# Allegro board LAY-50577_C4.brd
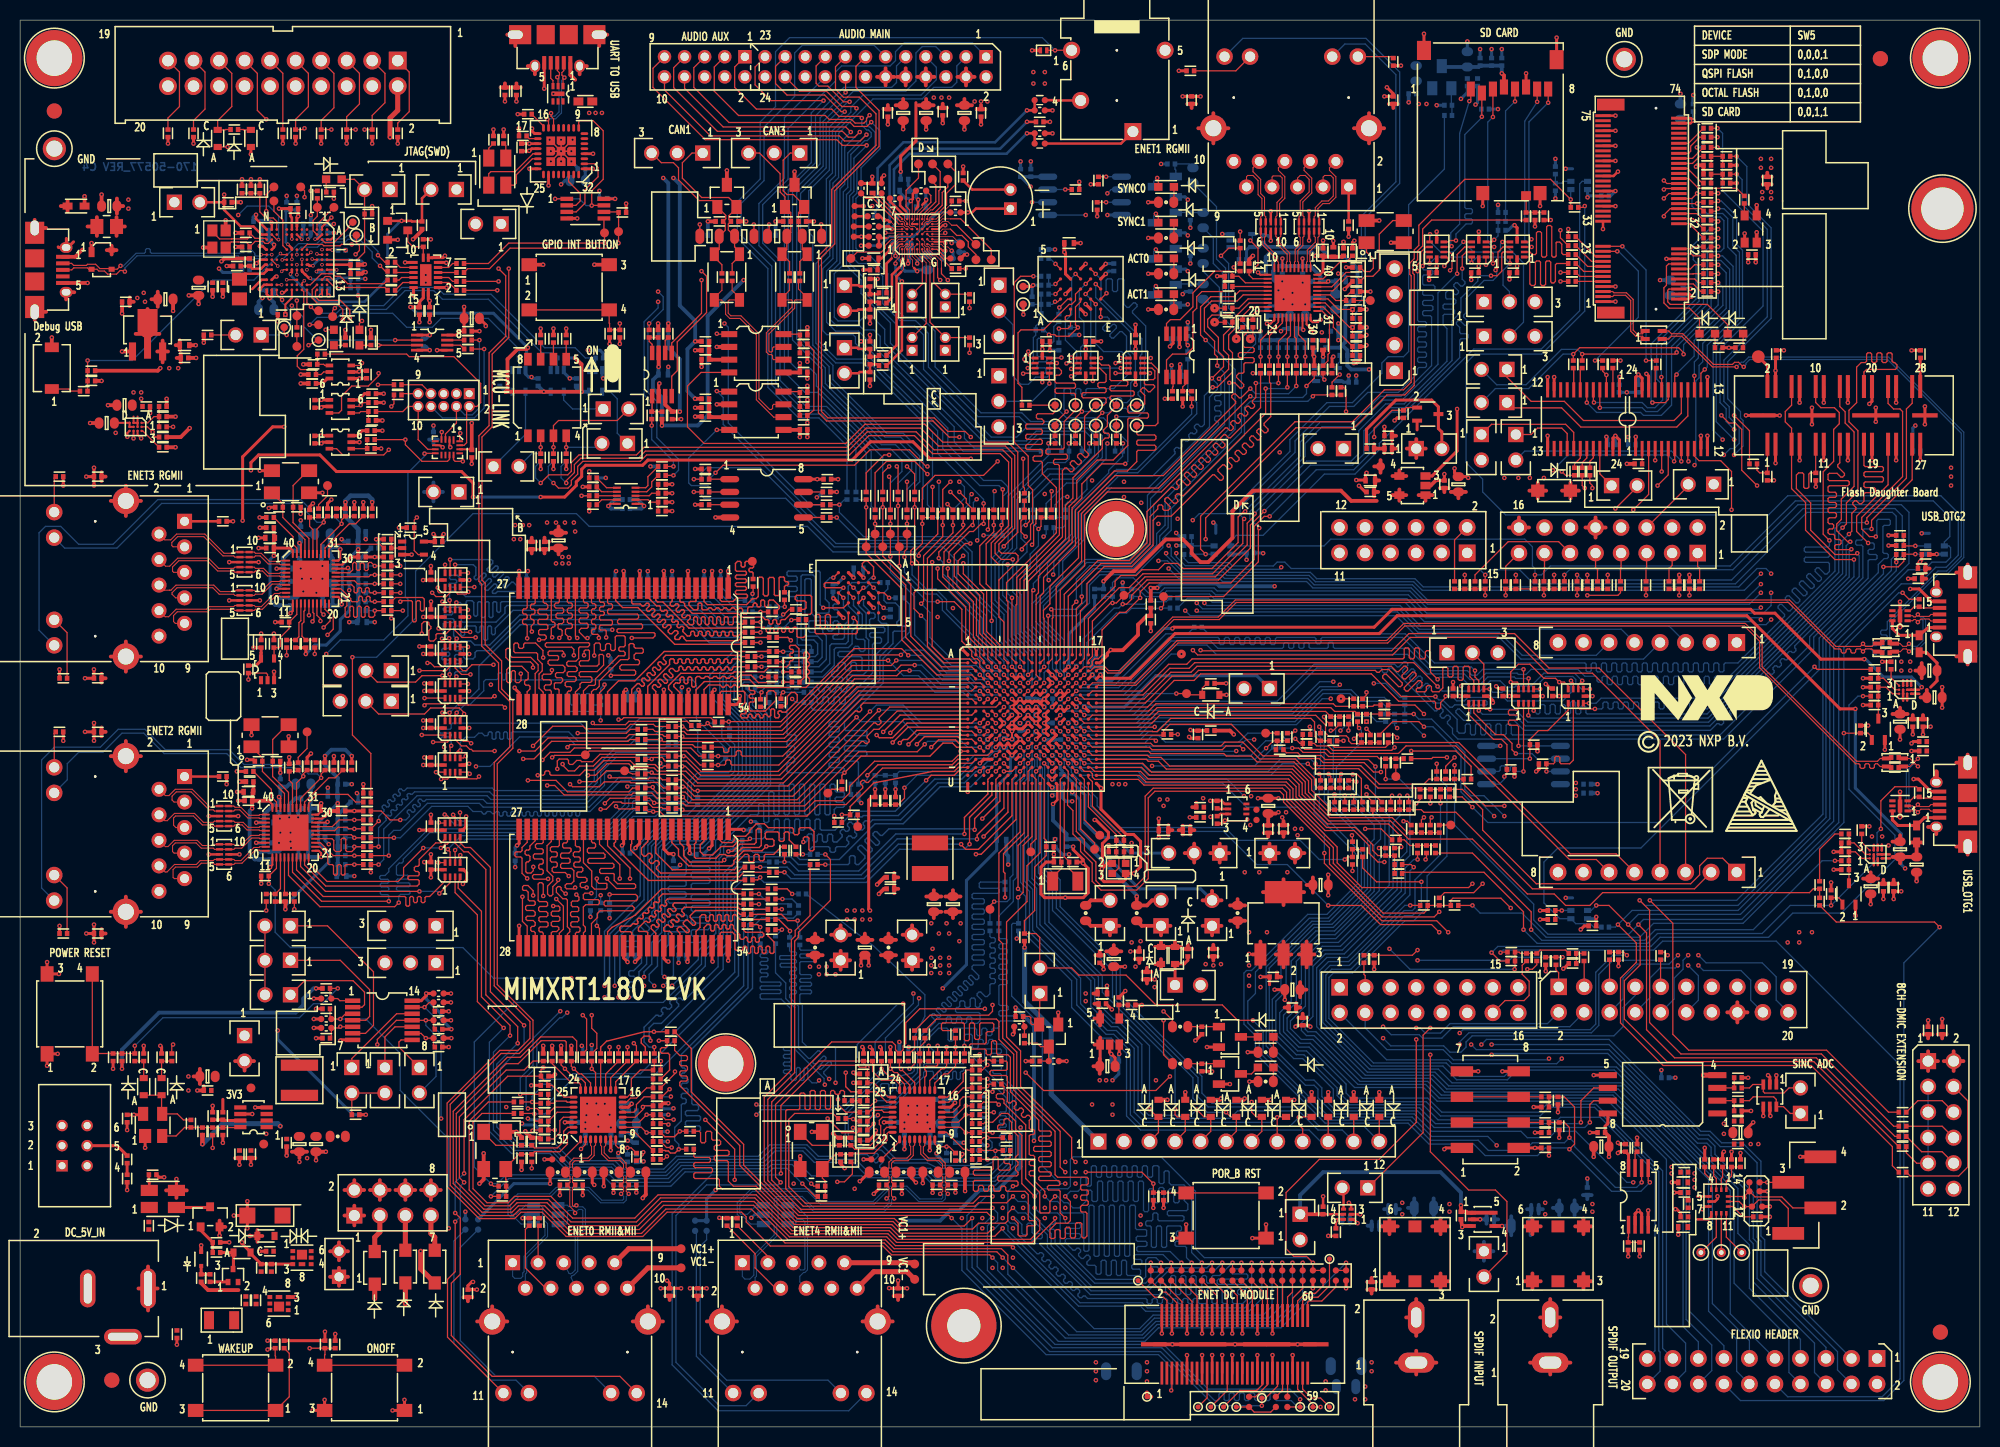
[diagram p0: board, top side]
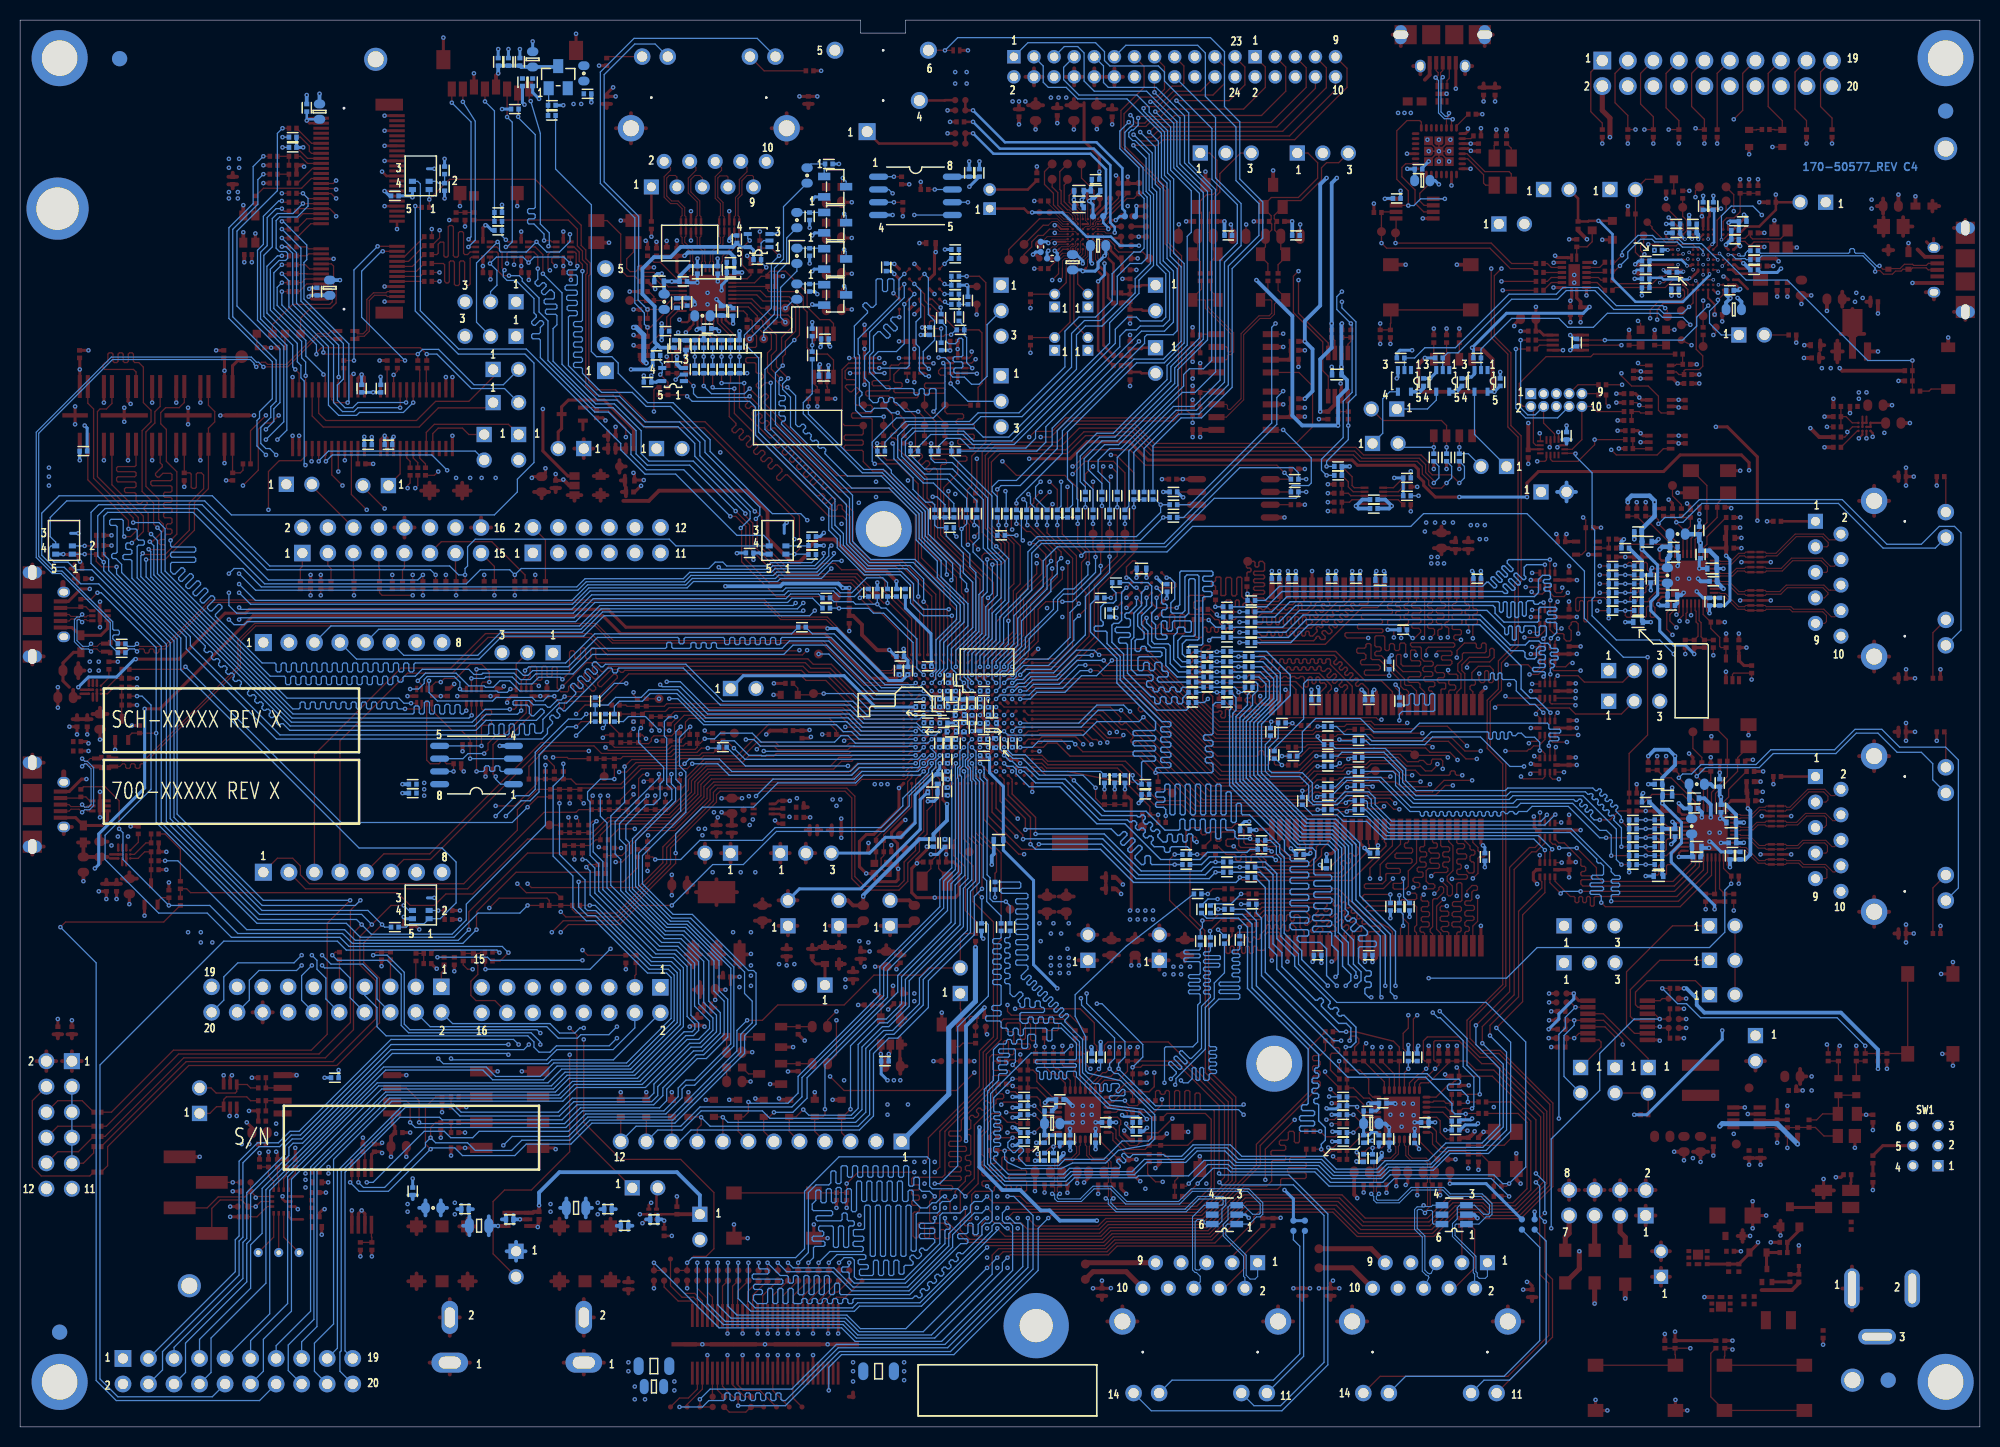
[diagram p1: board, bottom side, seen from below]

Outline 195 x 140 mm; copper layers: TOP, L2_GND_1, L3_INT_1, L4_PWR_1, L5_GND_2, BOTTOM. Coordinates in mm from the lower left corner of the outline.
Outline path: 0,140 106.88,140 106.88,138.71 111.37,138.71 111.37,140 195,140 195,0 0,0 0,140

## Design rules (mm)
constraint set DEFAULT: min track width 0.127
net group CAN1: nets N103603009 N103603017
net group CAN2: nets N100797464 N100797616
net group DBUG_USB_D: nets DBUG_USB_DM DBUG_USB_DP
net group DP1-USB: nets N101733827 N101733829
net group DP_N99833038: nets N99833038 N99833048
net group DP_N100169943: nets N100169943 N100169951
net group DP_OTG1: nets OTG1_DN OTG1_DP
net group DP_OTG2: nets OTG2_DN OTG2_DP
net group ECAT0_RX_DV: nets ECAT0_RX_DV PHY0_RXDV
net group ECAT0_RXCLK: nets ECAT0_RXCLK PHY0_RXC
net group ECAT0_RXD2: nets ECAT0_RXD2 PHY0_RXD2_INTB
net group ECAT0_RXD3: nets ECAT0_RXD3 PHY0_RXD3
net group ENET1_RGMII_RX_EN: nets ENET1_RGMII_RX_EN RXCTL_PHYAD2_1
net group ENET1_RGMII_RXC: nets ENET1_RGMII_RXC RXC_PHYAD1_1
net group ENET1_RGMII_RXD0: nets ENET1_RGMII_RXD0 RXD0_RXDLY_1
net group ENET1_RGMII_RXD1: nets ENET1_RGMII_RXD1 RXD1_TXDLY_1
net group ENET1_RGMII_RXD2: nets ENET1_RGMII_RXD2 RXD2_PLLOFF_1
net group ENET1_RGMII_RXD3: nets ENET1_RGMII_RXD3 RXD3_PHYAD0_1
net group ETH1_TRX0: nets PHY1_TRX0_N PHY1_TRX0_P
net group ETH1_TRX1: nets PHY1_TRX1_N PHY1_TRX1_P
net group ETH1_TRX2_: nets PHY1_TRX2_N PHY1_TRX2_P
net group ETH1_TRX3_: nets PHY1_TRX3_N PHY1_TRX3_P
net group ETH2_TRX0_: nets PHY2_TRX0_N PHY2_TRX0_P
net group ETH2_TRX1_: nets PHY2_TRX1_N PHY2_TRX1_P
net group ETH2_TRX2_: nets PHY2_TRX2_N PHY2_TRX2_P
net group ETH2_TRX3_: nets PHY2_TRX3_N PHY2_TRX3_P
net group ETH3_TRX0_: nets PHY3_TRX0_N PHY3_TRX0_P
net group ETH3_TRX1_: nets PHY3_TRX1_N PHY3_TRX1_P
net group ETH3_TRX2_: nets PHY3_TRX2_N PHY3_TRX2_P
net group ETH3_TRX3_: nets PHY3_TRX3_N PHY3_TRX3_P
net group FLEXSPI1_A_D4: nets FLEXSPI1_A_D4 GPIO_B2_03
net group FLEXSPI1_A_D5: nets FLEXSPI1_A_D5 GPIO_B2_04
net group FLEXSPI1_A_D6: nets FLEXSPI1_A_D6 GPIO_B2_05
net group FLEXSPI1_A_D7: nets FLEXSPI1_A_D7 GPIO_B2_06
net group FLEXSPI1_A_SS0_8: nets FLEXSPI1_A_SS0_8 N103609361
net group FLEXSPI2_A_SS0: nets FLEXSPI2_A_SS0 GPIO_EMC_B1_39_P
net group GPIO_EMC_B2_02: nets GPIO_EMC_B2_02 SEMC_D18
net group N103961253: nets N103961253 N103962432
net group N103961260: nets N103961260 N103962456
net group N105541476: nets N105541476 N105544244
net group PHY0_MDI0: nets PHY0_MDI0+ PHY0_MDI0-
net group PHY0_MDI1: nets PHY0_MDI1+ PHY0_MDI1-
net group PHY0_TXD2: nets ECAT0_TXD2 PHY0_TXD2
net group PHY0_TXD3: nets ECAT0_TXD3 PHY0_TXD3
net group PHY3_RGMII_RX_EN: nets PHY3_RGMII_RX_EN RXCTL_PHYAD2_3
net group PHY3_RGMII_RXC: nets PHY3_RGMII_RXC RXC_PHYAD1_3
net group PHY3_RGMII_RXD0: nets PHY3_RGMII_RXD0 RXD0_RXDLY_3
net group PHY3_RGMII_RXD1: nets PHY3_RGMII_RXD1 RXD1_TXDLY_3
net group PHY3_RGMII_RXD2: nets PHY3_RGMII_RXD2 RXD2_PLLOFF_3
net group PHY3_RGMII_RXD3: nets PHY3_RGMII_RXD3 RXD3_PHYAD0_3
net group PHY4_MDI0: nets PHY4_MDI0+ PHY4_MDI0-
net group PHY4_MDI1: nets PHY4_MDI1+ PHY4_MDI1-
net group SD1_CLK: nets N100768470 SD1_CLK
net group SD_PWREN_B: nets N101370712 SD_PWREN_B
net group SEMC_A5: nets GPIO_EMC_B1_14 SEMC_A5
net group SEMC_A6: nets GPIO_EMC_B1_15 SEMC_A6
net group SEMC_A9: nets GPIO_EMC_B1_18 SEMC_A9
net group SEMC_A11: nets GPIO_EMC_B1_19 SEMC_A11
net group SEMC_CKE: nets GPIO_EMC_B1_27 SEMC_CKE
net group SEMC_CS0: nets GPIO_EMC_B1_29 SEMC_CS0
net group SEMC_D19: nets GPIO_EMC_B2_03 SEMC_D19
net group SEMC_D20: nets GPIO_EMC_B2_04 SEMC_D20
net group SEMC_WE: nets GPIO_EMC_B1_28 SEMC_WE
net group USB-A: nets N101733775 N101733777
net group WIFI_SDIO_CLK: nets N101734331 WIFI_SDIO_CLK
net group WIFI_SDIO_CMD: nets N101734351 WIFI_SDIO_CMD
net group WIFI_SDIO_D0: nets N101734355 WIFI_SDIO_D0
net group WIFI_SDIO_D1: nets N101734367 WIFI_SDIO_D1
net group WIFI_SDIO_D2: nets N101734379 WIFI_SDIO_D2
net group WIFI_SDIO_D3: nets N101734391 WIFI_SDIO_D3
net group 3W: nets AUD_INT DMIC_CLK JTAG_DACK JTAG_NSRST JTAG_RTCK JTAG_TCK SAI1_MCLK SAI1_RX_BCLK SAI1_TX_BCLK
net group CONN_ENET_RD2: nets CONN_ENET_RD2 ECAT0_RXD1 ENET0_RXD1 ENET4_RGMII_RXD2 GPIO_EMC_B2_10 PHY0_RXD1 SEMC_D25
net group CONN_ENET_RD3: nets CONN_ENET_RD3 ECAT0_RXD0 ENET0_RXD0 ENET4_RGMII_RXD3 GPIO_EMC_B2_09 PHY0_RXD0 SEMC_D24
net group CONN_ENET_RXC: nets CONN_ENET_RXC ECAT0_TX_REF_CLK ENET0_TX_REF_CLK ENET4_RGMII_RXC GPIO_EMC_B2_08 PHY0_TXC SEMC_DM2
net group ECAT1-TX(U123): nets ECAT1_TX_REF_CLK ECAT1_TXD0 ECAT1_TXD1 ECAT1_TXEN
net group ECAT1_RX_DV: nets ECAT1_RX_DV FLEXSPI2_B_D1 GPIO_EMC_B1_32_P PHY4_RXDV SEMC_D10
net group ECAT1_RXCLK: nets ECAT1_RXCLK FLEXSPI2_A_D3 GPIO_EMC_B1_38_P PHY4_RXC SEMC_DM1
net group ECAT1_RXD0: nets CONN_ENET_RD0 ECAT1_RXD0 ENET4_RGMII_RXD0 ENET4_RXD0 FLEXSPI2_B_D3 GPIO_EMC_B1_30_P GPIO_EMC_B2_17 PHY4_RXD0 SEMC_D8 SEMC_DM3
net group ECAT1_RXD1: nets CONN_ENET_RD1 ECAT1_RXD1 ENET4_RGMII_RXD1 ENET4_RXD1 FLEXSPI2_B_D2 GPIO_EMC_B1_31_P GPIO_EMC_B2_18 PHY4_RXD1 SEMC_D9
net group ECAT1_RXD2: nets ECAT1_RXD2 FLEXSPI2_B_CLK GPIO_EMC_B1_34_P PHY4_RXD2_INTB SEMC_D12
net group ECAT1_RXD3: nets ECAT1_RXD3 FLEXSPI2_A_D0 GPIO_EMC_B1_35_P PHY4_RXD3 SEMC_D13
net group ECAT1_RXER: nets ECAT1_RXER ENET4_RXER FLEXSPI2_B_D0 GPIO_EMC_B1_33_P GPIO_EMC_B2_20 PHY4_RXER/FXEN SEMC_D11
net group ECAT1_TXD2: nets ECAT1_TXD2 FLEXSPI2_A_D2 GPIO_EMC_B1_37_P PHY4_TXD2 SEMC_D15
net group ECAT1_TXD3: nets ECAT1_TXD3 FLEXSPI2_A_D1 GPIO_EMC_B1_36_P PHY4_TXD3 SEMC_D14
net group ENET2_MII_CRS: nets CONN_ENET_RX_CTL ENET2_MII_CRS ENET4_CRS_DV ENET4_RGMII_RX_EN FLEXSPI2_A_DQS GPIO_EMC_B1_40_P GPIO_EMC_B2_19 PHY4_CRS_DV
net group ENET2_RGMII_TXD2: nets ENET2_RGMII_TXD2 GPIO_EMC_B1_25 SEMC_RAS
net group ENET2_RGMII_TXD3: nets ENET2_RGMII_TXD3 GPIO_EMC_B1_24 SEMC_CAS
net group FLEXSPI1_A-A: nets FLEXSPI1_A_CLK_8 FLEXSPI1_A_D0_8 FLEXSPI1_A_D1_8 FLEXSPI1_A_D2_8 FLEXSPI1_A_D3_8 N103609386
net group FLEXSPI1_A-P: nets FLEXSPI1_A_CLK FLEXSPI1_A_D0 FLEXSPI1_A_D1 FLEXSPI1_A_D2 FLEXSPI1_A_D3 FLEXSPI1_A_DQS FLEXSPI1_A_SS0
net group FLEXSPI1_A-U12: nets FLEXSPI1_A_CLK_4 FLEXSPI1_A_D0_4 FLEXSPI1_A_D1_4 FLEXSPI1_A_D2_4 FLEXSPI1_A_D3_4 FLEXSPI1_A_SS0_4
net group FLEXSPI1_B-P-U6-J71: nets FLEXSPI1_B_D4 FLEXSPI1_B_D5 FLEXSPI1_B_D6 FLEXSPI1_B_D7 FLEXSPI1_B_DQS
net group FLEXSPI1_B-SWITCH-J71: nets FLEXSPI1_B_CLK_8 FLEXSPI1_B_D0_8 FLEXSPI1_B_D1_8 FLEXSPI1_B_D2_8 FLEXSPI1_B_D3_8 FLEXSPI1_B_SS0_8
net group FLEXSPI1_B-SWITHC-U10: nets FLEXSPI1_B_CLK_4 FLEXSPI1_B_D0_4 FLEXSPI1_B_D1_4 FLEXSPI1_B_D2_4 FLEXSPI1_B_D3_4 FLEXSPI1_B_SS0_4
net group FLEXSPI2_A_CLK: nets ENET2_MII_COL FLEXSPI2_A_CLK GPIO_EMC_B1_41_P PHY4_COL
net group FLEXSPI_B-U6-SWITCH: nets FLEXSPI1_B_CLK FLEXSPI1_B_D0 FLEXSPI1_B_D1 FLEXSPI1_B_D2 FLEXSPI1_B_D3 FLEXSPI1_B_SS0
net group GPIO_EMC_B1_00: nets GPIO_EMC_B1_00 GPIO_EMC_B1_00_P SEMC_D0
net group GPIO_EMC_B1_01: nets GPIO_EMC_B1_01 GPIO_EMC_B1_01_P SEMC_D1
net group GPIO_EMC_B1_02: nets GPIO_EMC_B1_02 GPIO_EMC_B1_02_P SEMC_D2
net group GPIO_EMC_B1_03: nets GPIO_EMC_B1_03 GPIO_EMC_B1_03_P SEMC_D3
net group GPIO_EMC_B1_04: nets GPIO_EMC_B1_04 GPIO_EMC_B1_04_P SEMC_D4
net group GPIO_EMC_B1_05: nets GPIO_EMC_B1_05 GPIO_EMC_B1_05_P SEMC_D5
net group GPIO_EMC_B1_06: nets GPIO_EMC_B1_06 GPIO_EMC_B1_06_P SEMC_D6
net group GPIO_EMC_B1_07: nets GPIO_EMC_B1_07 GPIO_EMC_B1_07_P SEMC_D7
net group GPIO_EMC_B1_08: nets GPIO_EMC_B1_08 GPIO_EMC_B1_08_P SEMC_DM0
net group PHY0_TXD0: nets ECAT0_TXD0 ENET0_TXD0 GPIO_EMC_B2_05 PHY0_TXD0 SEMC_D21
net group PHY0_TXD1: nets ECAT0_TXD1 ENET0_TXD1 GPIO_EMC_B2_06 PHY0_TXD1 SEMC_D22
net group PHY0_TXEN: nets ECAT0_TXEN ENET0_TXEN GPIO_EMC_B2_07 PHY0_TXEN SEMC_D23
net group PHY2-RGMII_TX(U29): nets PHY2_RGMII_TX_EN PHY2_RGMII_TXC PHY2_RGMII_TXD0 PHY2_RGMII_TXD1
net group PHY3-RGMII-TX(U34): nets PHY3_RGMII_TX_EN PHY3_RGMII_TXC PHY3_RGMII_TXD0 PHY3_RGMII_TXD1 PHY3_RGMII_TXD2 PHY3_RGMII_TXD3
net group PHY4_TXD0: nets CONN_ENET_TD0 ENET4_RGMII_TXD0 ENET4_TXD0 GPIO_EMC_B2_13 PHY4_TXD0 SEMC_D28
net group PHY4_TXD1: nets CONN_ENET_TD1 ENET4_RGMII_TXD1 ENET4_TXD1 GPIO_EMC_B2_14 PHY4_TXD1 SEMC_D29
net group PHY4_TXEN: nets CONN_ENET_TX_CTL ENET4_RGMII_TX_EN ENET4_TXEN GPIO_EMC_B2_15 PHY4_TXEN SEMC_D30
net group POWER: nets DCDC_1V8_OUT FDC_ECC GND_RJ45_SHELL0 GND_RJ45_SHELL1 GND_RJ45_SHELL2 GND_RJ45_SHELL3 GND_RJ45_SHELL4 N99833017 N100054135 N100054253 N100054255 N100054568 N100169932 N100310756 N100526140 N100538772 N101241745 N102544921 PHY1_AVDD10 PHY1_AVDD33 PHY1_DVDD10 PHY2_AVDD10 PHY2_AVDD33 PHY2_DVDD10 PHY2_DVDDRG PHY3_AVDD10 PHY3_AVDD33 PHY3_DVDD10 PHY3_DVDD33 PHY3_DVDDRG PHY4_3V3 SPDIF_VCC VDD_AON_ANA VDD_AON_DIG VDD_BBSM_ANA VDD_BBSM_IN VDD_COIN_3V VDD_USB_1P8 VDD_USB_3P3 VDDA_1P0 VREF
net group RGMII-TX: nets ENET1_RGMII_TX_EN ENET1_RGMII_TXC ENET1_RGMII_TXD0 ENET1_RGMII_TXD1 ENET1_RGMII_TXD2 ENET1_RGMII_TXD3
net group SD1: nets SD1_CMD SD1_D0 SD1_D1 SD1_D2 SD1_D3
net group SEMC_A0: nets GPIO_EMC_B1_09 GPIO_EMC_B1_09_P SEMC_A0
net group SEMC_A1: nets GPIO_EMC_B1_10 GPIO_EMC_B1_10_P SEMC_A1
net group SEMC_A2: nets GPIO_EMC_B1_11 GPIO_EMC_B1_11_P SEMC_A2
net group SEMC_A3: nets CONN_ENET_TD2 ECAT0_RXER ENET0_RXER ENET4_RGMII_TXD2 GPIO_EMC_B1_12 GPIO_EMC_B2_12 PHY0_RXER/FXEN SEMC_A3 SEMC_D27
net group SEMC_A4: nets ENET2_RGMII_RX_EN GPIO_EMC_B1_13 RXCTL_PHYAD2_2 SEMC_A4
net group SEMC_A7: nets ENET2_RGMII_RXD0 GPIO_EMC_B1_16 RXD0_RXDLY_2 SEMC_A7
net group SEMC_A8: nets ENET2_RGMII_RXD1 GPIO_EMC_B1_17 RXD1_TXDLY_2 SEMC_A8
net group SEMC_A10: nets ENET2_RGMII_RXD3 GPIO_EMC_B1_23 RXD3_PHYAD0_2 SEMC_A10
net group SEMC_BA0: nets ENET2_RGMII_RXC GPIO_EMC_B1_21 RXC_PHYAD1_2 SEMC_BA0
net group SEMC_BA1: nets ENET2_RGMII_RXD2 GPIO_EMC_B1_22 RXD2_PLLOFF_2 SEMC_BA1
net group SEMC_CLK: nets GPIO_EMC_B1_26 N101094010 N101094248 SEMC_CLK
net group SEMC_D26: nets CONN_ENET_TD3 ENET0_CRS_DV ENET4_RGMII_TXD3 GPIO_EMC_B2_11 PHY0_CRS_DV SEMC_D26
net group SEMC_D31: nets CONN_ENET_TXC ENET4_RGMII_TXC ENET4_TX_REF_CLK GPIO_EMC_B2_16 PHY4_TXC SEMC_D31

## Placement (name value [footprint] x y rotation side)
BH1  SMTSO-M25  [MH244-166T]  191.27 121.24 90 top
BH12  MOUNTING HOLE  [MH256P130]  93.9 10.08 0 top
C1  1uF  [0402_CC]  24.85 17.48 180 top
C2  47uF  [CC1206]  24.36 21.03 180 top
C3  0.1uF  [0402_CC]  15.6 9.22 270 top
C4  0.01UF  [0402_CC]  25 15.83 90 top
C5  10uF  [CC0603_OV]  29.44 28.15 270 top
C6  10uF  [CC0603_OV]  27.79 28.15 270 top
C7  -  [F204]  26.52 28.27 270 top
C8  22uF  [CC0603_OV]  18.65 34.88 180 top
C9  -  [F204]  18.65 33.48 180 top
C10  0.22uF  [0402_CC]  20.17 29.42 270 top
C11  1000pF  [0402_CC]  22.97 27.13 270 top
C12  1000pF  [0402_CC]  21.82 27.13 270 top
C13  1000pF  [0402_CC]  12.3 36.78 90 top
C14  0.1uF  [0402_CC]  10.65 30.69 270 top
C15  1uF  [0402_CC]  15.09 36.78 270 top
C17  10uF  [CC0603_OV]  108.18 35.89 0 top
C18  0.1uF  [0402_CC]  108.95 36.4 180 bottom
C19  4.7uF  [CC0402_TOL0P15]  107.68 43.13 0 top
C20  0.1uF  [0402_CC]  107.68 42.12 0 top
C21  10uF  [CC0603_OV]  126.6 43.51 180 top
C22  0.1uF  [0402_CC]  126.6 41.73 180 top
C23  10uF  [CC0603_OV]  129.39 53.93 0 top
C24  0.1uF  [0402_CC]  124.69 44.78 180 top
C25  10uF  [CC0603_OV]  143.11 93.8 90 top
C26  0.1uF  [0402_CC]  141.71 93.8 90 top
C27  4.7uF  [CC0402_TOL0P15]  134.35 94.19 180 top
C28  0.1uF  [0402_CC]  134.35 93.04 180 top
C29  1uF  [0402_CC]  138.54 132.67 180 bottom
C30  1uF  [0402_CC]  147.43 135.84 90 bottom
C31  0.1uF  [0402_CC]  31.35 8.21 90 top
C32  0.1uF  [0402_CC]  9.25 36.78 270 top
C33  0.1uF  [0402_CC]  25.38 8.21 90 top
C34  1uF  [0402_CC]  104.12 58.12 270 bottom
C35  2.2UF  [0402_CC]  102.8 64.85 270 bottom
C36  0.1uF  [0402_CC]  102.47 57.74 0 top
C37  18pF  [0402_CC]  103.23 56.21 180 top
C38  18pF  [0402_CC]  104.76 56.21 0 top
C39  0.1uF  [0402_CC]  102.77 63.25 270 bottom
C42  4.7uF  [CC0402_TOL0P15]  103.69 64.47 270 bottom
C43  4.7uF  [CC0402_TOL0P15]  104.2 63.15 180 bottom
C44  1uF  [0402_CC]  104.68 70.08 180 bottom
C45  0.1uF  [0402_CC]  117.2 68.91 270 top
C46  0.22uF  [0402_CC]  105.49 71.68 180 bottom
C47  2.2UF  [0402_CC]  102.75 66.42 90 bottom
C48  1uF  [0402_CC]  103.1 70.06 180 bottom
C49  1uF  [0402_CC]  103.54 68.02 90 bottom
C51  4.7uF  [CC0402_TOL0P15]  101.5 70.84 0 bottom
C53  1uF  [0402_CC]  99.49 72.04 90 bottom
C54  1uF  [0402_CC]  101.17 72.01 90 bottom
C55  4.7uF  [CC0402_TOL0P15]  100.3 72.04 90 bottom
C56  4.7uF  [CC0402_TOL0P15]  101.09 69.61 270 bottom
C57  2.2UF  [0402_CC]  101.91 68.02 90 bottom
C58  4.7uF  [CC0402_TOL0P15]  113.77 59.39 180 top
C59  -  [F204]  100.28 70.44 270 bottom
C60  22uF  [CC0603_OV]  84.05 47.7 270 top
C61  -  [F204]  99.13 68.44 180 bottom
C62  4.7uF  [CC0402_TOL0P15]  97.99 68.05 90 bottom
C63  -  [F204]  86.09 62.31 90 top
C64  0.22uF  [0402_CC]  86.09 64.47 270 bottom
C65  2.2UF  [0402_CC]  96.25 68.02 90 bottom
C66  10uF  [CC0603_OV]  108.82 46.56 270 top
C68  -  [F204]  86.59 54.69 180 top
C69  22uF  [CC0603_OV]  92.82 52.02 270 top
C70  10uF  [CC0603_OV]  90.91 52.02 270 top
C71  2.2UF  [0402_CC]  86.59 53.55 180 top
C72  -  [F204]  107.42 46.56 270 top
C73  100pF  [0402_CC]  118.47 73.99 0 top
C74  4.7PF  [0402_CC]  108.69 57.23 180 top
C75  4.7PF  [0402_CC]  110.22 57.23 0 top
C76  2.2UF  [0402_CC]  99.09 73.23 0 bottom
C77  2.2UF  [0402_CC]  104.71 75.69 0 bottom
C78  2.2UF  [0402_CC]  103.5 72.04 90 bottom
C79  2.2UF  [0402_CC]  102.6 74.42 90 bottom
C80  4.7uF  [CC0402_TOL0P15]  102.32 69.19 180 bottom
C81  2.2UF  [0402_CC]  102.72 68.02 90 bottom
C82  2.2UF  [0402_CC]  101.96 72.85 270 bottom
C83  4.7uF  [CC0402_TOL0P15]  98.3 70.03 0 bottom
C84  2.2UF  [0402_CC]  98.62 71.24 90 bottom
C85  1uF  [0402_CC]  107.42 76.66 180 bottom
C86  1uF  [0402_CC]  102.29 71.65 180 bottom
C87  1uF  [0402_CC]  107.55 75.26 90 bottom
C88  10PF  [0402_CC]  83.04 62.94 0 bottom
C89  1uF  [0402_CC]  106.66 75.26 90 bottom
C90  4.7uF  [CC0402_TOL0P15]  97.64 58.42 0 bottom
C91  2.2UF  [0402_CC]  99.09 66.78 0 bottom
C92  22uF  [CC0603_OV]  144 136.1 90 bottom
C93  2.2UF  [0402_CC]  146.41 135.84 90 bottom
C94  -  [F204]  145.27 135.84 90 bottom
C95  18pF  [0402_CC]  147.43 119.08 0 bottom
C96  18pF  [0402_CC]  147.43 120.86 180 bottom
C98  1uF  [CC0402_TOL0P2]  115.04 104.6 180 bottom
C99  1uF  [0402_CC]  155.94 63.07 0 bottom
C100  0.1uF  [0402_CC]  155.94 63.96 0 bottom
C101  0.1uF  [0402_CC]  108.82 115.39 90 bottom
C102  4.7uF  [CC0402_TOL0P15]  104.37 117.81 0 top
C103  1uF  [0402_CC]  99.55 124.79 90 bottom
C104  0.1uF  [0402_CC]  100.56 124.79 90 bottom
C105  1uF  [0402_CC]  80.32 94.31 0 top
C106  0.1uF  [0402_CC]  80.24 93.04 180 bottom
C107  22uF  [CC0603_OV]  53.57 88.22 90 top
C108  4.7uF  [CC0402_TOL0P15]  59.67 84.28 180 bottom
C109  0.1uF  [0402_CC]  62.08 84.41 180 bottom
C110  0.1uF  [0402_CC]  68.43 84.41 180 bottom
C111  0.1uF  [0402_CC]  50.02 84.41 0 bottom
C112  0.1uF  [0402_CC]  60.81 72.34 180 bottom
C113  0.1uF  [0402_CC]  66.15 72.34 180 bottom
C114  0.1uF  [0402_CC]  70.08 84.41 180 bottom
C115  0.1uF  [0402_CC]  64.5 84.41 0 bottom
C116  4.7uF  [CC0402_TOL0P15]  83.42 85.42 0 bottom
C117  0.1uF  [0402_CC]  80.88 83.49 90 bottom
C118  4.7uF  [CC0402_TOL0P15]  73.13 59.39 0 bottom
C119  0.1uF  [0402_CC]  52.18 87.71 90 top
C120  0.1uF  [0402_CC]  65.89 46.94 180 bottom
C121  0.1uF  [0402_CC]  67.67 56.97 180 bottom
C122  0.1uF  [0402_CC]  65 55.96 270 bottom
C123  0.1uF  [0402_CC]  60.31 57.1 0 bottom
C124  0.1uF  [0402_CC]  60.81 46.94 180 bottom
C125  0.1uF  [0402_CC]  49.26 56.72 270 bottom
C126  0.1uF  [0402_CC]  156.44 49.86 180 top
C165  0.1uF  [0402_CC]  134.47 14.05 90 top
C166  0.01UF  [0402_CC]  136.51 21.67 180 bottom
C167  0.1uF  [0402_CC]  129.65 21.54 90 top
C168  0.1uF  [0402_CC]  143.36 21.03 270 top
C169  0.1uF  [0402_CC]  150.73 21.67 0 bottom
C170  0.1uF  [0402_CC]  50.65 20.4 90 top
C176  10PF  [0402_CC]  54.08 24.08 180 top
C177  10PF  [0402_CC]  55.61 24.08 0 top
C178  10PF  [0402_CC]  59.42 24.08 180 top
C179  10PF  [0402_CC]  60.94 24.08 0 top
C180  0.1uF  [0402_CC]  51.67 20.4 90 top
C181  1500pF  [0402_CC]  44.56 13.29 270 top
C182  0.1uF  [0402_CC]  56.88 36.78 90 bottom
C183  0.22uF  [0402_CC]  132.19 119.59 270 top
C184  22pF  [0402_CC]  132.95 115.39 180 top
C185  22pF  [0402_CC]  132.95 114 180 top
C186  1500pF  [0402_CC]  116.57 132.03 270 top
C187  4.7uF  [CC0402_TOL0P15]  129.65 107.65 270 top
C188  0.1uF  [0402_CC]  128.63 107.77 270 top
C189  0.1uF  [0402_CC]  127.62 115.14 270 bottom
C190  0.1uF  [0402_CC]  125.58 115.14 270 bottom
C191  0.1uF  [0402_CC]  129.01 114 180 bottom
C192  4.7uF  [CC0402_TOL0P15]  131.43 114 0 bottom
C193  0.1uF  [0402_CC]  129.65 116.92 90 top
C194  0.1uF  [0402_CC]  124.31 114.89 0 bottom
C195  4.7uF  [CC0402_TOL0P15]  130.66 116.92 90 top
C196  0.1uF  [0402_CC]  124.31 115.9 0 bottom
C197  4.7uF  [CC0402_TOL0P15]  125.2 111.08 90 bottom
C198  0.1uF  [0402_CC]  124.06 110.95 90 bottom
C199  4.7uF  [CC0402_TOL0P15]  128.76 107.65 270 bottom
C200  0.1uF  [0402_CC]  126.6 109.3 180 bottom
C201  22PF  [0402_CC]  128.76 105.23 90 top
C202  22PF  [0402_CC]  132.95 112.98 0 top
C203  4.7uF  [CC0402_TOL0P15]  129.65 111.84 90 bottom
C204  0.1uF  [0402_CC]  128.63 111.97 90 bottom
C205  0.22uF  [0402_CC]  20.17 64.72 0 top
C206  22pF  [0402_CC]  23.73 66.25 180 top
C207  22pF  [0402_CC]  25.51 66.25 0 top
C208  1500pF  [0402_CC]  7.73 69.17 0 top
C209  4.7uF  [CC0402_TOL0P15]  31.1 62.82 180 bottom
C210  0.1uF  [0402_CC]  31.98 61.29 0 top
C211  0.1uF  [0402_CC]  25.76 61.55 270 bottom
C212  0.1uF  [0402_CC]  25.89 64.09 90 bottom
C213  0.1uF  [0402_CC]  24.62 58.12 0 bottom
C214  4.7uF  [CC0402_TOL0P15]  24.75 60.15 0 bottom
C215  0.1uF  [0402_CC]  24.87 56.85 90 bottom
C216  0.1uF  [0402_CC]  22.71 62.31 180 top
C217  4.7uF  [CC0402_TOL0P15]  22.71 63.2 180 top
C218  0.1uF  [0402_CC]  23.86 56.85 90 bottom
C219  4.7uF  [CC0402_TOL0P15]  28.17 57.74 180 bottom
C220  0.1uF  [0402_CC]  28.17 56.72 180 bottom
C221  4.7uF  [CC0402_TOL0P15]  31.98 54.82 0 bottom
C222  0.1uF  [0402_CC]  30.33 59.13 270 bottom
C223  22PF  [0402_CC]  34.52 61.29 180 top
C224  22PF  [0402_CC]  26.78 65.61 90 top
C225  4.7uF  [CC0402_TOL0P15]  28.43 62.56 180 bottom
C226  0.1uF  [0402_CC]  28.43 61.55 180 bottom
C227  0.22uF  [0402_CC]  20.17 90.12 0 top
C228  22pF  [0402_CC]  25.76 91.52 180 top
C229  22pF  [0402_CC]  27.54 91.52 0 top
C230  1500pF  [0402_CC]  7.73 74.5 0 top
C231  4.7uF  [CC0402_TOL0P15]  33.13 88.09 180 bottom
C232  0.1uF  [0402_CC]  34.02 86.57 0 top
C233  0.1uF  [0402_CC]  27.92 89.21 90 bottom
C234  0.1uF  [0402_CC]  26.52 84.15 0 bottom
C235  0.1uF  [0402_CC]  27.79 86.82 270 bottom
C236  4.7uF  [CC0402_TOL0P15]  26.65 85.42 0 bottom
C237  0.1uF  [0402_CC]  25.89 82.12 90 bottom
C238  0.1uF  [0402_CC]  26.9 82.12 90 bottom
C239  4.7uF  [CC0402_TOL0P15]  24.87 88.47 180 top
C240  0.1uF  [0402_CC]  24.87 87.45 180 top
C241  4.7uF  [CC0402_TOL0P15]  30.59 82.76 180 bottom
C242  0.1uF  [0402_CC]  30.71 81.74 180 bottom
C243  4.7uF  [CC0402_TOL0P15]  34.02 80.09 0 bottom
C244  0.1uF  [0402_CC]  32.75 84.41 270 bottom
C245  22PF  [0402_CC]  36.56 86.57 180 top
C246  22PF  [0402_CC]  28.81 90.88 90 top
C247  4.7uF  [CC0402_TOL0P15]  30.46 86.57 180 bottom
C248  0.1uF  [0402_CC]  30.46 87.58 180 bottom
C263  10uF  [CC0603_OV]  184.13 53.8 270 top
C264  0.1uF  [0402_CC]  185.4 53.67 270 top
C267  10uF  [CC0603_OV]  187.05 70.18 270 top
C268  0.1uF  [0402_CC]  188.32 70.06 270 top
C270  0.1uF  [0402_CC]  68.18 101.42 180 top
C271  1uF  [0402_CC]  68.18 100.54 180 top
C272  1uF  [0402_CC]  77.96 99.27 0 top
C273  56PF  [0402_CC]  71.1 119.97 180 top
C274  0.01UF  [0402_CC]  68.05 118.57 0 bottom
C275  56PF  [0402_CC]  69.58 119.97 180 top
C276  0.1uF  [0402_CC]  68.18 107.14 180 top
C277  1uF  [0402_CC]  68.18 106.25 180 top
C278  1uF  [0402_CC]  77.96 104.98 0 top
C279  56PF  [0402_CC]  77.83 119.97 180 top
C280  0.01UF  [0402_CC]  74.78 118.57 0 bottom
C281  56PF  [0402_CC]  76.31 119.97 180 top
C282  0.1uF  [0402_CC]  167.87 125.55 180 top
C283  10uF  [CC0603_OV]  165.21 130.89 90 bottom
C284  0.1uF  [0402_CC]  166.48 131.27 90 bottom
C285  0.1uF  [0402_CC]  165.46 112.98 90 bottom
C286  0.1uF  [0402_CC]  167.87 124.67 180 top
C287  10uF  [CC0603_OV]  164.19 113.36 90 bottom
C288  0.1uF  [0402_CC]  172.32 116.66 180 top
C289  0.1uF  [0402_CC]  160.38 97.74 180 bottom
C290  0.1uF  [0402_CC]  161.02 103.33 270 bottom
C291  0.1uF  [0402_CC]  159.11 103.33 270 bottom
C292  0.1uF  [0402_CC]  158.35 97.74 180 bottom
C293  220pF  [0402_CC]  151.8 46.36 270 top
C294  220pF  [0402_CC]  154.47 46.11 180 top
C295  220pF  [0402_CC]  159.04 46.87 270 top
C296  10uF  [CC0603_OV]  93.96 130.76 270 top
C297  0.1uF  [0402_CC]  95.61 130.76 270 top
C298  10uF  [CC0603_OV]  90.15 130.76 270 top
C299  0.1uF  [0402_CC]  91.8 130.89 270 top
C300  10uF  [CC0603_OV]  87.86 130.76 270 top
C301  0.1uF  [0402_CC]  86.34 130.76 270 top
C303  1000PF  [0402_CC]  170.92 30.43 0 top
C304  1000PF  [0402_CC]  157.33 29.29 180 top
C305  10uF  [CC0603_OV]  157.33 27.89 180 top
C306  220pF  [0402_CC]  170.92 34.75 0 top
C307  220pF  [0402_CC]  170.92 31.45 0 top
C308  4.7uF  [CC0402_TOL0P15]  165.46 19.89 180 top
C309  0.1uF  [0402_CC]  165.59 20.91 180 top
C310  0.1uF  [0402_CC]  165.59 23.32 180 top
C311  4.7uF  [CC0402_TOL0P15]  165.46 24.34 180 top
C312  1uF  [0402_CC]  151.75 27.76 0 top
C317  0.039uF  [0402_CC]  159.75 27.76 90 top
C323  18pF  [0402_CC]  22.46 117.43 180 top
C324  18pF  [0402_CC]  22.46 118.82 180 top
C326  0.01UF  [0402_CC]  7.09 104.09 0 top
C338  10uF  [CC0603_OV]  8.87 121.49 180 top
C346  0.1uF  [0402_CC]  30.33 113.24 180 bottom
C347  0.1uF  [0402_CC]  32.01 117.1 0 bottom
C348  0.1uF  [0402_CC]  23.6 119.97 180 bottom
C349  0.1uF  [0402_CC]  30.54 114.91 180 bottom
C350  0.1uF  [0402_CC]  28.56 118.82 0 bottom
C351  0.1uF  [0402_CC]  27.29 121.24 180 top
C352  22uF  [CC0603_OV]  17.76 113.36 270 top
C353  22uF  [CC0603_OV]  24.49 111.2 180 bottom
C354  0.1uF  [0402_CC]  24.87 113.11 180 bottom
C355  0.1uF  [0402_CC]  20.17 113.49 270 top
C356  2.2UF  [0402_CC]  19.16 113.49 270 top
C358  0.1uF  [0402_CC]  22.46 115.14 180 bottom
C359  0.1uF  [0402_CC]  12.55 101.55 0 top
C360  10uF  [CC0603_OV]  10.39 101.68 180 top
C361  4.7uF  [CC0603_OV]  187.05 57.48 90 top
C362  4.7uF  [CC0603_OV]  190.48 72.6 0 top
C363  4.7uF  [CC0603_OV]  189.97 75.26 180 top
C364  4.7uF  [CC0603_OV]  188.7 55.96 270 top
C365  4.7uF  [CC0603_OV]  8.62 99.9 180 top
C370  0.1uF  [0402_CC]  10.52 111.97 180 top
C371  0.1uF  [0402_CC]  16.36 106.38 0 top
C372  10uF  [CC0603_OV]  14.46 112.22 0 top
C373  4.7uF  [CC0402_TOL0P15]  16.36 107.65 0 top
C385  0.1uF  [0402_CC]  40.11 107.9 270 bottom
C386  0.1uF  [0402_CC]  34.47 104.73 90 top
C387  0.1uF  [0402_CC]  29.06 103.84 180 top
C388  0.1uF  [0402_CC]  29.32 98.25 270 top
C389  0.1uF  [0402_CC]  34.91 99.14 0 top
C390  0.1uF  [0402_CC]  29.32 101.81 270 top
C391  0.1uF  [0402_CC]  35.03 102.82 0 top
C392  0.1uF  [0402_CC]  23.86 123.14 90 top
C393  0.1uF  [0402_CC]  44.56 109.04 0 top
C394  10uF  [CC0603_OV]  44.94 110.31 0 top
C395  0.1uF  [0402_CC]  44.94 96.85 270 top
C397  0.1uF  [0402_CC]  40.75 111.05 270 top
C398  0.1uF  [0402_CC]  39.73 111.05 270 top
C399  10uF  [CC0603_OV]  124.19 61.8 90 top
C400  10uF  [CC0603_OV]  171.18 29.29 0 top
C401  0.1uF  [0402_CC]  144.76 114.86 180 top
C402  0.1uF  [0402_CC]  148.57 114.86 180 top
C403  0.1uF  [0402_CC]  140.57 114.86 180 top
C404  0.1uF  [0402_CC]  142.58 73.1 90 top
C405  0.1uF  [0402_CC]  147.53 73.1 90 top
C406  0.1uF  [0402_CC]  152.48 73.1 90 top
C407  0.1uF  [0402_CC]  102.09 108.03 0 top
C408  0.1uF  [0402_CC]  110.98 108.28 90 top
C409  0.1uF  [0402_CC]  106.41 108.03 0 top
C410  0.22uF  [0402_CC]  58.02 122.25 180 bottom
C411  0.22uF  [0402_CC]  50.53 130.63 180 top
C412  0.22uF  [0402_CC]  55.86 125.17 180 bottom
C413  0.22uF  [0402_CC]  49.89 127.33 270 top
C414  10uF  [CC0603_OV]  55.48 124.03 180 bottom
C431  0.1uF  [0402_CC]  40.87 84.66 90 top
C432  0.1uF  [0402_CC]  40.87 80.98 90 top
C433  0.1uF  [0402_CC]  40.87 77.29 90 top
C434  0.1uF  [0402_CC]  40.87 73.61 90 top
C435  0.1uF  [0402_CC]  40.87 69.93 90 top
C436  0.1uF  [0402_CC]  40.87 66.25 90 top
C452  0.1uF  [0402_CC]  40.87 59.77 90 top
C455  0.1uF  [0402_CC]  40.87 55.83 90 top
C462  0.1uF  [0402_CC]  191.24 39.45 90 top
C463  0.1uF  [0402_CC]  189.85 39.45 90 top
C464  1uF  [0402_CC]  60.31 92.28 180 bottom
C465  0.1uF  [0402_CC]  60.31 91.39 180 bottom
C466  0.1uF  [0402_CC]  113.77 22.94 270 top
C468  0.1uF  [0402_CC]  189.59 86.82 180 top
C469  0.1uF  [0402_CC]  122.41 86.97 0 bottom
C470  0.1uF  [0402_CC]  157.71 122.51 0 bottom
C471  0.1uF  [0402_CC]  188.7 97.11 180 bottom
C472  0.1uF  [0402_CC]  189.08 106.76 90 top
C473  2.2UF  [0402_CC]  174.73 106.76 90 top
C475  0.1uF  [0402_CC]  58.78 28.65 90 bottom
C476  22uF  [CC0603_OV]  60.56 30.18 180 bottom
C477  0.1uF  [0402_CC]  59.42 32.21 180 bottom
C478  0.1uF  [0402_CC]  55.23 30.3 0 bottom
C479  -  [F204]  56.24 28.63 90 bottom
C480  -  [F204]  52.18 28.65 180 top
C481  22pF  [0402_CC]  50.91 28.4 90 top
C482  22pF  [0402_CC]  49.89 26.75 270 top
C507  -  [F204]  70.34 20.4 90 top
C508  -  [F204]  71.35 20.4 90 top
C509  1500pF  [0402_CC]  67.42 13.41 270 top
C510  -  [F204]  83.93 28.53 0 top
C511  10PF  [0402_CC]  92.69 24.08 0 top
C512  10PF  [0402_CC]  85.83 24.08 180 top
C513  10PF  [0402_CC]  91.17 24.08 180 top
C514  10PF  [0402_CC]  87.36 24.08 0 top
C515  22pF  [0402_CC]  81.64 26.75 270 top
C516  22pF  [0402_CC]  81.51 28.4 90 top
C517  -  [F204]  87.48 36.78 90 bottom
C518  -  [F204]  87.99 28.65 90 bottom
C519  -  [F204]  90.53 28.65 90 bottom
C520  -  [F204]  91.55 32.59 180 bottom
C521  -  [F204]  86.98 30.3 0 bottom
C522  22uF  [CC0603_OV]  92.31 30.18 180 bottom
C523  0.22uF  [0402_CC]  114.92 108.28 0 bottom
C524  0.22uF  [0402_CC]  64.88 100.66 270 top
C525  1uF  [CC0402_TOL0P2]  63.99 104.73 0 bottom
C526  1500pF  [0402_CC]  189.34 67.26 180 top
C527  1500pF  [0402_CC]  189.21 85.42 180 top
C528  1500pF  [0402_CC]  49.38 132.92 270 top
C529  -  [F204]  119.11 60.4 270 top
C530  -  [F204]  119.11 61.93 90 top
C562  0.1uF  [CC0402_25]  30.46 42.62 180 top
C563  0.1uF  [CC0402_25]  41.64 43.13 0 top
C565  0.1uF  [CC0402_25]  30.46 40.59 180 top
C567  0.1uF  [CC0402_25]  30.46 39.7 180 top
C569  0.1uF  [CC0402_25]  41.64 38.69 0 top
C571  0.1uF  [CC0402_25]  41.64 40.46 0 top
C573  0.1uF  [CC0402_25]  41.64 42.24 0 top
C574  -  [F204]  55.35 103.96 90 bottom
C575  -  [F204]  51.54 103.96 90 bottom
C576  -  [F204]  47.73 103.96 90 bottom
C577  0.1UF  [CC0402_25]  99.42 39.83 180 top
C578  0.1uF  [CC0402_25]  102.85 36.4 0 top
C579  4.7uF  [CC0603_OV]  90.28 115.9 90 bottom
C580  4.7uF  [CC0603_OV]  87.74 117.55 0 bottom
C581  0.1uF  [CC0402_25]  93.45 117.43 270 bottom
C582  4.7uF  [CC0402_TOL0P15]  84.94 116.28 180 top
C583  4.7uF  [CC0402_TOL0P15]  89.64 121.36 0 bottom
C584  4.7uF  [CC0402_TOL0P15]  87.99 123.01 180 bottom
C585  4.7uF  [CC0402_TOL0P15]  89.64 123.01 0 bottom
C586  0.1uF  [CC0402_25]  92.31 116.28 180 bottom
C587  2.2UF  [CC0402_25]  87.05 122.25 0 top
C588  4.7uF  [CC0402_TOL0P15]  84.82 123.27 90 top
C589  1uF  [CC0402_25]  84.94 118.44 180 top
C590  2.2UF  [CC0402_25]  83.67 123.27 90 top
C591  2.2UF  [CC0402_25]  85.71 123.27 90 top
C592  1uF  [CC0402_25]  93.07 120.86 180 top
C593  1uF  [CC0402_25]  89.64 123.01 180 top
C594  15PF  [0402_CC]  84.56 107.65 270 top
C595  15PF  [0402_CC]  84.56 113.87 270 top
C596  15PF  [0402_CC]  84.56 106.12 270 top
C597  15PF  [0402_CC]  84.56 112.35 270 top
C598  15PF  [0402_CC]  84.56 104.6 270 top
C599  15PF  [0402_CC]  84.56 110.82 270 top
C600  0.1uF  [CC0402_25]  84.84 120.47 180 top
C601  0.1uF  [CC0402_25]  84.94 119.46 180 top
C602  1000pF  [CC0402_25]  101.45 131.02 0 top
C603  1000pF  [CC0402_25]  101.45 128.73 0 top
C604  -  [F204]  58.65 108.79 270 top
C887  10uF  [CC1206_OV]  131.93 6.05 0 bottom
C902  10uF  [CC1206_OV]  109.58 5.54 180 bottom
C903  -  [F204]  123.68 118.19 90 bottom
C908  -  [F204]  132.57 103.96 0 bottom
C909  -  [F204]  23.98 77.93 90 top
C910  -  [F204]  41.64 88.09 0 top
D1  MM5Z5V1ST1G  [SOD_523_1P4]  18.01 16.72 90 top
D2  RB521S30  [SOD523]  22.08 17.36 180 top
D3  LED_RED-GRN  [LED_DUAL_3025MM_SM]  14.2 22.68 0 top
D4  RB521S30  [SOD523]  12.3 33.86 270 top
D5  RB521S30  [SOD523]  14.08 33.86 270 top
D6  GREEN  [LED_0603]  123.93 35.77 180 top
D7  RED  [LED_0603]  123.93 38.81 180 top
D8  RB521S30  [SOD523]  113.52 46.92 270 top
D9  RB521S30  [SOD523]  114.92 46.92 270 top
D10  PESD3V3L1UB  [SOD523]  135.24 31.7 90 top
D11  PESD3V3L1UB  [SOD523]  132.7 31.7 90 top
D12  PESD3V3L1UB  [SOD523]  130.16 31.7 90 top
D13  PESD3V3L1UB  [SOD523]  128.5 31.7 90 top
D14  PESD3V3L1UB  [SOD523]  125.96 31.7 90 top
D15  PESD3V3L1UB  [SOD523]  123.55 31.7 90 top
D16  PESD3V3L1UB  [SOD523]  121.01 31.7 90 top
D17  PESD3V3L1UB  [SOD523]  118.47 31.7 90 top
D18  PESD3V3L1UB  [SOD523]  115.93 31.7 90 top
D19  PESD3V3L1UB  [SOD523]  113.26 31.7 90 top
D20  PESD3V3L1UB  [SOD523]  118.47 72.85 0 top
D21  NUP2105L  [SOT-23]  70.33 122.5 0 top
D22  NUP2105L  [SOT-23]  77.06 122.5 0 top
D23  RED  [LED_0603]  170.67 108.79 180 top
D24  RED  [LED_0603]  167.87 108.79 180 top
D25  RB521S30  [SOD523]  22.96 128.22 270 top
D26  RB521S30  [SOD523]  19.66 128.22 270 top
D27  MBR120VLSFT1G  [SOD-123]  152.63 93.17 0 top
D28  BAV99DW  [SC70-6]  174.1 32.97 180 top
D29  GREEN LED  [LED_0603]  31.22 108.41 90 top
D30  GREEN LED  [LED_0603]  33.76 108.41 90 top
D31  GREEN  [LED_0603]  114.03 123.4 180 top
D32  RED  [LED_0603]  114.03 119.84 180 top
D33  RED  [LED_0603]  114.03 116.28 180 top
D35  GREEN  [LED_0603]  114.03 112.73 180 top
D37  LED_RED-GRN  [LED_DUAL_3025MM_SM]  47.48 124.92 270 top
D39  RED  [LED_0603]  31.22 124.16 0 top
D41  MBR120VLSFT1G  [SOD-123]  35.29 15.83 90 top
D42  MBR120VLSFT1G  [SOD-123]  38.33 15.95 90 top
D43  MBR120VLSFT1G  [SOD-123]  41.26 15.95 90 top
D46  LXES1UTAA1-157  [DFN2_0P65_1P05X0P65MM]  101.83 136.98 180 top
F1  5A/32V  [FUSE_3P4X1P8]  20.05 10.62 0 top
FL1  ACT45B-510-2P  [IND4_4P7X3P4_SMT]  70.33 114.43 270 top
FL2  ACT45B-510-2P  [IND4_4P7X3P4_SMT]  77.06 114.43 270 top
H1  .635" LONG  [SPACER_139T]  3.41 136.22 0 top
H2  .635" LONG  [SPACER_139T]  191.07 136.22 0 top
H3  .635" LONG  [SPACER_139T]  3.41 4.48 0 top
H4  .635" LONG  [SPACER_139T]  191.07 4.48 270 top
H5  .635" LONG  [SPACER_139T]  109.07 89.36 0 top
H6  .635" LONG  [SPACER_139T]  70.21 36.15 0 top
J1  HDR 2X4  [HDR2X4_2P54_TH]  33.25 21.03 90 top
J2  CON_1_PWR  [CON3_PWR_TH]  12.73 13.77 270 top
J3  HDR 1X2  [HDR102]  22.33 38.94 0 top
J4  HDR 1X2  [HDR102]  124.31 57.1 90 top
J5  HDR 1X2  [HDR102]  138.92 97.36 90 top
J6  HDR 1X2  [HDR102]  113.52 49.86 180 top
J7  HDR 1X2  [HDR102]  114.92 43.97 90 top
J8  HDR 1X12  [HDR112_B]  107.3 28.4 90 top
J9  HDR 1X2  [HDR102]  118.6 49.86 180 top
J10  HDR 1X2  [HDR102]  124.31 73.48 270 top
J11  HDR_1X3  [HDR103]  119.36 57.1 270 top
J12  HDR 1X2  [HDR102]  81.64 46.43 180 top
J14  HDR 1X2  [HDR102]  88.75 46.43 180 top
J15  95220030-14RRF  [CON_SDCARD_95220]  146.28 129.87 0 top
J23  HDR 1X2  [HDR102]  127.36 21.16 0 top
J24  CON_2_RCA  [CON2_RCA_RA_TH]  138.91 6.39 90 top
J25  HDR 1X2  [HDR102]  134.09 23.79 270 top
J26  HDR 1X2  [HDR102]  145.65 17.48 0 top
J27  CON_2_RCA  [CON2_RCA_RA_TH]  152.25 6.39 90 top
J28  7499211121A  [CON_RJ45_2LED_TH_A]  49 16.34 180 top
J29  RJ-45  [CON_RJ45_10_2LED_TH]  132.19 123.4 0 top
J30  RJ-45  [CON_RJ45_10_2LED_TH]  16.36 64.72 90 top
J31  RJ-45  [CON_RJ45_10_2LED_TH]  16.36 90.12 90 top
J32  7499211121A  [CON_RJ45_2LED_TH_A]  71.86 16.34 180 top
J33  USB AB 5  [CON9_MICROAB_USB_SHELL_TH]  193.78 61.93 90 top
J34  HDR_1X3  [HDR103]  67.92 126.77 270 top
J35  HDR_1X3  [HDR103]  77.57 126.77 270 top
J36  M.2 MINI CARD  [CON_67_0P5_22X7P75_RA]  161.4 121.24 90 top
J37  BH25420B301  [HDR_2X10M_100_TH]  37.57 135.97 270 top
J39  CON 2x8  [CON_2X8_SKT_100_TH]  131.29 43.74 0 top
J41  CON 2x6  [CON_SKT2X6_TH]  143.98 86.97 0 top
J44  CON 2x10  [CON_SKT2X10_TH]  153.09 43.79 90 top
J45  CON 2x8  [CON_2X8_SKT_100_TH]  166.92 86.96 180 top
J46  HDR 1X2  [HDR102]  168.51 93.8 270 top
J47  HDR_2x12  [HDR2X12_2MM_TH]  96.12 136.35 180 top
J48  HDR_2x5  [HDR2X5_2MM_TH]  72.12 136.35 180 top
J49  HDR 1X2  [HDR102]  177.15 31.19 180 top
J50  HDR_4X1  [HDR104_STAG_TSM_SM]  177.53 23.07 180 top
J51  SSM-104-L-DV  [CON_2X4_SKT_100_SM]  146.28 31.57 180 top
J53  USB AB 5  [CON9_MICROAB_USB_SHELL_TH]  1.45 115.14 270 top
J56  HDR 2X5  [CON2X5_50_TH_A]  44.68 102.82 180 top
J57  HDR_1X3  [HDR103]  145.65 108.54 90 top
J58  HDR_1X3  [HDR103]  141.97 77.04 90 top
J59  HDR_1X3  [HDR103]  97.39 104.6 0 top
J60  USB AB 5  [CON9_MICROAB_USB_SHELL_TH]  53.45 138.55 180 top
J62  SKT_1X8  [CON_1X8_SKT_2P54_TH]  170.8 78.06 270 top
J63  HDR_1X3  [HDR103]  36.94 72.21 270 top
J65  HDR_1X3  [HDR103]  41.38 46.18 270 top
J67  HDR 2X6  [HDR2X6_2P54_TH]  189.85 36.4 0 top
J68  USB AB 5  [CON9_MICROAB_USB_SHELL_TH]  193.78 80.85 90 top
J69  HDR 2X10  [HDR210_344H]  184.77 6.81 270 top
J70  SKT_1X8  [CON_1X8_SKT_2P54_TH]  170.8 55.2 270 top
J71  CON 2X14  [CON_014_QSE_DP_F]  181.46 100.66 0 top
J72  HDR_1X3  [HDR103]  41.38 49.86 270 top
J73  HDR_1X3  [HDR103]  36.94 75.26 270 top
J75  HDR_1X3  [HDR103]  97.39 113.62 0 top
J76  HDR_1X3  [HDR103]  145.65 111.97 90 top
J77  HDR 1X2  [HDR102]  108.44 49.86 180 top
J78  HDR 1X2  [HDR102]  147.94 105.23 270 top
J79  HDR 1X2  [HDR102]  147.94 101.93 270 top
J80  HDR 1X2  [HDR102]  145.4 98.76 0 top
J81  HDR 1X2  [HDR102]  148.82 98.76 0 top
J88  HDR 1X2  [HDR102]  26.9 46.43 270 top
J89  HDR 1X2  [HDR102]  39.73 35.77 0 top
J90  HDR 1X2  [HDR102]  26.9 43 270 top
J91  HDR 1X2  [HDR102]  26.9 49.86 270 top
J92  HDR 1X2  [HDR102]  101.45 43.13 180 top
J93  HDR 1X2  [HDR102]  36.3 35.77 0 top
J94  HDR 1X2  [HDR102]  33 35.77 0 top
J95  HDR 1X2  [HDR102]  82.02 107.39 0 top
J96  HDR 1X2  [HDR102]  82.02 113.62 0 top
J97  HDR_1X2  [HDR1X2_50MIL]  92.06 107.14 180 top
J98  HDR_1X2  [HDR1X2_50MIL]  92.06 111.46 180 top
J99  HDR_1X2  [HDR1X2_50MIL]  88.75 111.46 180 top
J100  HDR_1X2  [HDR1X2_50MIL]  88.75 107.14 180 top
J101  Audio Jack  [CON5_AUD_JACK_RA_TH_SJ-43514]  110.72 128.9 270 top
J102  HDR 1X2  [HDR102]  60.43 97.87 270 top
J103  HDR 1X2  [HDR102]  58.02 101.3 90 top
J104  HDR 1X2  [HDR102]  47.1 95.58 90 top
J105  HDR 1X2  [HDR102]  158.35 93.68 90 top
J108  HDR 1X5  [HDR105]  136.76 105.11 180 top
J134  QSH-030-01-L-D-A-K-TR  [CON_60S_QSH_SM_A]  120.86 8.22 0 top
J135  HDR 1X2  [HDR102]  131.68 97.36 270 top
JP1  SHORT_100mil  [100MIL_TH]  31.73 14.94 90 top
JP2  HDR 1X2  [HDR102]  43.41 123.14 270 top
JP3  HDR 1X2  [HDR102]  36.81 123.14 270 top
JP4  HDR 1X2  [HDR102]  15.35 121.87 90 top
JP5  HDR 1X2  [HDR102]  43.67 93.04 270 top
JP6  HDR 1X2  [HDR102]  47.86 119.71 270 top
JP7  HDR 1X2  [HDR102]  23.98 108.66 270 top
L1  1uH  [IND_4020]  27.79 34.5 90 top
L2  120 Ohm  [0402_CC]  124.19 59.49 90 top
L3  120 Ohm  [0402_CC]  118.47 69.29 0 top
L4  120 Ohm  [0402_CC]  116.06 59.39 180 top
L5  4.7uH  [IND_4P2X4P2]  90.53 56.59 270 top
L6  120 Ohm  [0402_CC]  112.5 80.34 90 top
L7  120 Ohm  [0402_CC]  112.5 81.87 270 top
L8  120 Ohm  [0402_CC]  102.75 72.85 270 bottom
L9  120 Ohm  [0402_CC]  50.91 87.71 270 top
L15  300Ohms@100MHz  [IND_1P8X1MM_SM]  188.7 59.01 270 top
L16  90OHM  [IND4_CHOKE_0805]  186.54 66.12 180 top
L18  300Ohms@100MHz  [IND_1P8X1MM_SM]  188.96 77.93 270 top
L19  90OHM  [IND4_CHOKE_0805]  185.65 77.55 180 top
L21  90OHM  [IND4_CHOKE_0805]  162.54 108.66 0 top
L22  120 Ohm  [0402_CC]  170.92 28.15 0 top
L23  4.7uH  [IND_0805]  21.82 113.24 90 top
L24  330 OHM  [IND_0805]  8.62 119.46 0 top
L25  300Ohms@100MHz  [IND_1P8X1MM_SM]  5.57 121.49 180 top
L29  BLM18KG121TZ1  [IND_0603]  56.24 131.9 180 top
L33  120 Ohm  [0402_CC]  173.84 124.03 90 top
L34  120 Ohm  [0402_CC]  61.32 28.65 90 bottom
L36  120 Ohm  [0402_CC]  93.07 28.65 90 bottom
L37  120 Ohm  [IND_0402]  101.45 132.03 0 top
L38  120 Ohm  [IND_0402]  101.45 127.71 0 top
NOREF  -  []  53.07 98.63 0 top
NOREF#2  -  []  130.2 115.47 0 top
NOREF#3  -  []  23.29 63.52 0 top
NOREF#4  -  []  59.96 29.32 90 top
NOREF#5  -  []  209.27 32.59 90 top
NOREF#6  -  []  59.16 16.34 0 top
NOREF#7  -  []  8.03 38 0 top
NOREF#8  -  []  42.78 81.3 0 top
NOREF#9  -  []  87.51 28.62 90 top
NOREF#10  -  []  101.71 104.71 90 top
NOREF#11  -  []  147.47 118.2 90 top
NOREF#12  -  []  113.3 59.39 0 top
NOREF#13  -  []  42.13 55.45 0 top
NOREF#14  -  []  84.37 116.61 0 top
NOREF#15  -  []  105.32 104.87 0 top
NOREF#16  -  []  192.17 96.92 90 top
NOREF#17  -  []  188.7 58.16 90 top
NOREF#18  -  []  115.64 104.25 0 top
NOREF#19  -  []  43.78 58.68 90 top
NOREF#20  -  []  33.05 86.61 0 top
NOREF#21  -  []  10.89 99.52 90 top
NOREF#22  -  []  147.46 71.95 90 top
NOREF#23  -  []  167.72 23.98 0 top
NOREF#24  -  []  139.69 136.98 0 top
NOREF#25  -  []  116.84 104.25 90 top
NOREF#26  -  []  100.3 71.56 90 top
NOREF#27  -  []  90.22 122.69 90 top
NOREF#28  -  []  41.67 116.43 0 top
NOREF#29  -  []  139.21 122.2 0 top
NOREF#30  -  []  170.82 23.98 90 top
NOREF#31  -  []  22.24 63.2 0 top
NOREF#32  -  []  126.03 110.5 90 top
NOREF#33  -  []  173.86 97.79 90 top
NOREF#34  -  []  189.85 23.7 0 top
NOREF#35  -  []  31.83 9.22 90 top
NOREF#36  -  []  60.25 83.95 0 top
NOREF#37  -  []  0.36 129.9 90 top
NOREF#38  -  []  60.01 28.57 90 top
NOREF#39  -  []  7.18 37.12 90 top
NOREF#40  -  []  144.44 117.92 0 top
NOREF#41  -  []  105.25 104.59 0 top
NOREF#42  -  []  139.21 122.2 90 top
NOREF#43  -  []  43.78 54.75 90 top
NOREF#44  -  []  44.06 54.68 0 top
NOREF#45  -  []  102.36 136.01 0 top
NOREF#46  -  []  140.25 116.92 90 top
NOREF#47  -  []  148.95 116.27 90 top
NOREF#48  -  []  110.38 56.43 0 top
NOREF#49  -  []  95.92 58.75 0 top
NOREF#50  -  []  129.32 111.26 0 top
NOREF#51  -  []  157.37 71.95 90 top
NOREF#52  -  []  148.94 72.72 0 top
NOREF#53  -  []  4.72 121.49 0 top
NOREF#54  -  []  45.61 54.68 90 top
NOREF#55  -  []  116.02 23.28 0 top
NOREF#56  -  []  153.76 53.74 0 top
NOREF#57  -  []  -3.45 -2.21 0 top
NOREF#58  -  []  31.83 9.22 0 top
NOREF#59  -  []  157.37 102.19 0 top
NOREF#60  -  []  155.96 123.95 90 top
NOREF#61  -  []  116.02 18.78 90 top
NOREF#62  -  []  42.78 66.57 0 top
NOREF#63  -  []  106.73 105.37 90 top
NOREF#64  -  []  189.78 72.67 90 top
NOREF#65  -  []  5 127.21 0 top
NOREF#66  -  []  92.63 50.29 90 top
NOREF#67  -  []  148.25 116.92 90 top
NOREF#68  -  []  2.68 45.08 0 top
NOREF#69  -  []  9.11 115.21 90 top
NOREF#70  -  []  14.27 4.65 0 top
NOREF#71  -  []  26.08 85.75 0 top
NOREF#72  -  []  54.34 98.63 90 top
NOREF#73  -  []  167.19 20.22 90 top
NOREF#74  -  []  107.1 41.66 90 top
NOREF#75  -  []  83.29 7.45 90 top
NOREF#76  -  []  31.02 61.34 0 top
NOREF#77  -  []  166.04 20.22 0 top
NOREF#78  -  []  152.42 71.95 90 top
NOREF#79  -  []  168.77 21.26 0 top
NOREF#80  -  []  30.74 6.99 90 top
NOREF#81  -  []  168.09 22.43 90 top
NOREF#82  -  []  84.21 3.37 90 top
NOREF#83  -  []  139.69 136.98 0 top
NOREF#84  -  []  81.69 85.75 0 top
NOREF#85  -  []  -161.18 -102.54 0 top
NOREF#86  -  []  39.15 115.88 0 top
NOREF#87  -  []  60.43 7.45 90 top
NOREF#88  -  []  145.91 71.95 0 top
NOREF#89  -  []  129.32 107.07 0 top
NOREF#90  -  []  55.76 28.62 90 top
NOREF#91  -  []  26.6 88.8 90 top
NOREF#92  -  []  165.05 112.24 90 top
NOREF#93  -  []  113.7 60.86 0 top
NOREF#94  -  []  189.46 78.83 0 top
NOREF#95  -  []  87.42 122.69 90 top
NOREF#96  -  []  145.53 122.78 90 top
NOREF#97  -  []  165.05 112.24 90 top
NOREF#98  -  []  173.86 97.79 90 top
NOREF#99  -  []  31.67 61.34 90 top
NOREF#100  -  []  162.03 68.15 0 top
NOREF#101  -  []  33.44 80.41 0 top
NOREF#102  -  []  27.23 85.75 90 top
NOREF#103  -  []  97.02 68.62 0 top
NOREF#104  -  []  3.16 103.29 90 top
NOREF#105  -  []  130.95 114 0 top
NOREF#106  -  []  121.01 90.02 90 top
NOREF#107  -  []  159.63 36.07 90 top
NOREF#108  -  []  39.6 101.55 90 top
NOREF#109  -  [unnamed#2]  9.12 4.65 0 top
NOREF#110  -  []  173.86 97.79 0 top
NOREF#111  -  []  30.9 -3.44 90 top
NOREF#112  -  []  40.12 116.35 0 top
NOREF#113  -  []  10.23 8.97 90 top
NOREF#114  -  []  108.65 55.08 90 top
NOREF#115  -  []  129.08 108.22 0 top
NOREF#116  -  []  51.54 110.31 0 top
NOREF#117  -  []  107.2 43.13 0 top
NOREF#118  -  []  164.99 19.89 0 top
NOREF#119  -  []  165.05 112.24 90 top
NOREF#120  -  []  49 7.45 0 top
NOREF#121  -  []  88.43 50.29 0 top
NOREF#122  -  []  43.41 102.82 0 top
NOREF#123  -  []  63.39 105.08 0 top
NOREF#124  -  []  46.97 10.49 0 top
NOREF#125  -  []  14.23 38 90 top
NOREF#126  -  []  1.51 107.51 90 top
NOREF#127  -  []  42.78 56.16 0 top
NOREF#128  -  []  129.3 24.13 90 top
NOREF#129  -  []  44.06 58.61 0 top
NOREF#130  -  []  63.51 104.73 0 top
NOREF#131  -  []  44.06 72.46 0 top
NOREF#132  -  []  53.76 -25.28 90 top
NOREF#133  -  []  411.71 390.98 0 top
NOREF#134  -  []  29 62.23 0 top
NOREF#135  -  []  45.61 58.61 90 top
NOREF#136  -  []  102.48 104.59 90 top
NOREF#137  -  []  97.99 67.57 90 top
NOREF#138  -  []  189.26 90.02 0 top
NOREF#139  -  []  33.54 80.09 0 top
NOREF#140  -  []  139.69 136.98 0 top
NOREF#141  -  []  87.52 123.01 0 top
NOREF#142  -  []  130.99 116.34 0 top
NOREF#143  -  []  72.66 59.39 0 top
NOREF#144  -  []  167.19 24.66 90 top
NOREF#145  -  []  60.43 7.45 90 top
NOREF#146  -  []  155.82 71.95 0 top
NOREF#147  -  []  157.98 35 0 top
NOREF#148  -  []  192.01 90.02 90 top
NOREF#149  -  []  93.69 63.44 0 top
NOREF#150  -  []  103.41 136.01 90 top
NOREF#151  -  []  55.06 32.82 0 top
NOREF#152  -  []  147.49 85.62 90 top
NOREF#153  -  []  17.47 1.64 90 top
NOREF#154  -  []  32.19 86.24 90 top
NOREF#155  -  []  42.78 60.09 0 top
NOREF#156  -  []  55.06 29.32 90 top
NOREF#157  -  []  173.86 97.79 0 top
NOREF#158  -  []  82.94 85.42 0 top
NOREF#159  -  []  144.64 73.43 0 top
NOREF#160  -  []  97.83 70.03 0 top
NOREF#161  -  []  145.53 122.78 90 top
NOREF#162  -  []  0 0 90 top
NOREF#163  -  []  44.06 65.09 0 top
NOREF#164  -  []  79.48 16.34 0 top
NOREF#165  -  []  31.16 82.43 0 top
NOREF#166  -  []  162.77 111.24 90 top
NOREF#167  -  []  153.36 122.2 90 top
NOREF#168  -  []  97.67 67.47 90 top
NOREF#169  -  []  0 0 0 top
NOREF#170  -  []  149.07 41.2 90 top
NOREF#171  -  []  52.12 96.86 90 top
NOREF#172  -  []  30.3 6.14 0 top
NOREF#173  -  []  56.62 16.34 0 top
NOREF#174  -  []  153.89 72.72 0 top
NOREF#175  -  []  91.76 28.57 0 top
NOREF#176  -  []  120.46 86.85 90 top
NOREF#177  -  []  43.78 76.21 90 top
NOREF#178  -  []  164.99 24.34 0 top
NOREF#179  -  []  -0.92 18.37 0 top
NOREF#180  -  []  42.13 59.39 0 top
NOREF#181  -  []  42.13 76.91 0 top
NOREF#182  -  []  154.3 51.4 0 top
NOREF#183  -  []  192.39 23.7 90 top
NOREF#184  -  []  114.35 59.71 90 top
NOREF#185  -  []  185.24 56.57 90 top
NOREF#186  -  []  101 104.87 0 top
NOREF#187  -  []  14.71 133.43 90 top
NOREF#188  -  []  64.59 105.08 90 top
NOREF#189  -  []  30.62 62.82 0 top
NOREF#190  -  []  114.57 104.6 0 top
NOREF#191  -  []  84.37 115.96 90 top
NOREF#192  -  []  139.69 136.98 0 top
NOREF#193  -  []  10.23 8.97 0 top
NOREF#194  -  []  102.56 70.19 90 top
NOREF#195  -  []  185.24 56.57 90 top
NOREF#196  -  []  189.2 58.91 90 top
NOREF#197  -  []  16.94 107.32 90 top
NOREF#198  -  []  24.17 60.48 0 top
NOREF#199  -  []  34.59 80.41 90 top
NOREF#200  -  []  45.61 65.09 90 top
NOREF#201  -  []  43.78 68.84 90 top
NOREF#202  -  []  189.8 87.67 0 top
NOREF#203  -  []  103.72 63.15 0 top
NOREF#204  -  []  49 16.34 0 top
NOREF#205  -  []  90.22 121.04 90 top
NOREF#206  -  []  192.39 23.7 90 top
NOREF#207  -  []  42.78 70.25 0 top
NOREF#208  -  []  158.27 110.89 90 top
NOREF#209  -  []  94.87 139.47 0 top
NOREF#210  -  []  28.75 57.41 0 top
NOREF#211  -  []  10.65 100.21 0 top
NOREF#212  -  []  187.76 73.76 0 top
NOREF#213  -  []  42.78 84.99 0 top
NOREF#214  -  []  189.2 59.91 0 top
NOREF#215  -  []  110.27 104.87 0 top
NOREF#216  -  []  37.37 6.99 0 top
NOREF#217  -  []  155.96 51.4 90 top
NOREF#218  -  []  173.86 97.79 0 top
NOREF#219  -  []  87.51 33.52 0 top
NOREF#220  -  []  161.21 136.1 0 top
NOREF#221  -  []  130.47 111.26 90 top
NOREF#222  -  []  89.07 123.34 0 top
NOREF#223  -  []  31.04 86.24 0 top
NOREF#224  -  []  191.46 86.85 90 top
NOREF#225  -  []  32.56 55.14 90 top
NOREF#226  -  [unnamed#2]  3.41 130.95 0 top
NOREF#227  -  []  186.86 56.28 90 top
NOREF#228  -  []  29.9 57.41 90 top
NOREF#229  -  []  45.61 76.14 90 top
NOREF#230  -  []  144.44 116.92 90 top
NOREF#231  -  []  74.12 134.35 90 top
NOREF#232  -  []  153.76 126.3 0 top
NOREF#233  -  []  97.73 70.36 0 top
NOREF#234  -  []  45.61 83.51 90 top
NOREF#235  -  []  33.7 86.61 90 top
NOREF#236  -  []  106.03 104.71 90 top
NOREF#237  -  []  45.47 96.86 0 top
NOREF#238  -  []  43.78 65.16 90 top
NOREF#239  -  []  147.64 133.34 90 top
NOREF#240  -  []  150.87 71.95 0 top
NOREF#241  -  []  73.71 59.71 90 top
NOREF#242  -  []  31.41 55.14 0 top
NOREF#243  -  []  91.71 29.32 90 top
NOREF#244  -  []  193.73 37.82 0 top
NOREF#245  -  []  156.51 53.74 90 top
NOREF#246  -  []  53.76 -3.44 0 top
NOREF#247  -  []  145.92 118.2 0 top
NOREF#248  -  []  108.58 50.32 0 top
NOREF#249  -  []  44.06 68.77 0 top
NOREF#250  -  []  155.96 50.57 90 top
NOREF#251  -  []  141.73 118.2 0 top
NOREF#252  -  []  104.01 65.04 0 top
NOREF#253  -  []  104.77 61.67 90 top
NOREF#254  -  []  14.71 135.97 0 top
NOREF#255  -  []  50.66 111.16 0 top
NOREF#256  -  []  129.65 107.17 90 top
NOREF#257  -  []  -0.92 18.37 90 top
NOREF#258  -  []  158.27 110.89 90 top
NOREF#259  -  []  43.97 99.59 0 top
NOREF#260  -  []  131.29 41.2 0 top
NOREF#261  -  []  99.97 71.46 0 top
NOREF#262  -  []  145.53 122.78 90 top
NOREF#263  -  []  43.97 93.89 90 top
NOREF#264  -  []  108.57 -3.72 90 top
NOREF#265  -  []  71.86 16.34 0 top
NOREF#266  -  []  86.81 29.32 90 top
NOREF#267  -  []  39.15 113.38 90 top
NOREF#268  -  [unnamed#2]  185.1 136.16 0 top
NOREF#269  -  []  188.16 72.96 90 top
NOREF#270  -  []  101.84 69.19 0 top
NOREF#271  -  []  148.25 117.92 0 top
NOREF#272  -  []  43.78 79.89 90 top
NOREF#273  -  []  130.66 116.44 90 top
NOREF#274  -  []  64.12 136.35 0 top
NOREF#275  -  []  72.56 59.71 0 top
NOREF#276  -  []  188.4 72.67 0 top
NOREF#277  -  []  101.09 69.14 90 top
NOREF#278  -  []  53.76 -3.44 90 top
NOREF#279  -  []  143.28 118.2 90 top
NOREF#280  -  []  188.16 72.96 90 top
NOREF#281  -  []  25.32 60.48 90 top
NOREF#282  -  []  111.75 104.59 90 top
NOREF#283  -  []  172.57 62.31 0 top
NOREF#284  -  []  118.8 87.67 0 top
NOREF#285  -  []  157.37 102.19 90 top
NOREF#286  -  []  108.65 56.08 0 top
NOREF#287  -  []  184.04 57.38 0 top
NOREF#288  -  []  105.88 -3.72 0 top
NOREF#289  -  []  30.9 -3.44 0 top
NOREF#290  -  []  84.82 122.79 90 top
NOREF#291  -  []  128.76 107.17 90 top
NOREF#292  -  []  104.77 61.67 0 top
NOREF#293  -  []  57.74 110.31 90 top
NOREF#294  -  []  107.1 41.66 0 top
NOREF#295  -  []  107.69 63.44 90 top
NOREF#296  -  []  103.69 63.99 90 top
NOREF#297  -  []  24.54 6.99 0 top
NOREF#298  -  []  89.07 121.69 0 top
NOREF#299  -  []  45.61 72.46 90 top
NOREF#300  -  []  139.69 136.98 0 top
NOREF#301  -  []  71.86 7.45 0 top
NOREF#302  -  []  139.21 137.55 0 top
NOREF#303  -  []  81.69 85.1 90 top
NOREF#304  -  []  129.65 111.36 90 top
NOREF#305  -  []  98.88 70.36 90 top
NOREF#306  -  []  61.35 3.37 90 top
NOREF#307  -  []  29.99 86.57 0 top
NOREF#308  -  []  130.85 114.32 90 top
NOREF#309  -  []  149.73 118.2 0 top
NOREF#310  -  []  97.17 58.42 0 top
NOREF#311  -  []  101.41 70.19 0 top
NOREF#312  -  []  124.88 110.5 0 top
NOREF#313  -  []  30.15 62.23 90 top
NOREF#314  -  []  12.73 13.77 90 top
NOREF#315  -  []  149.59 73.43 0 top
NOREF#316  -  []  156.51 126.3 90 top
NOREF#317  -  []  24.4 88.47 0 top
NOREF#318  -  []  15.79 107.32 0 top
NOREF#319  -  []  143.98 72.72 0 top
NOREF#320  -  []  179.75 14.05 0 top
NOREF#321  -  []  42.13 73.23 0 top
NOREF#322  -  []  158.27 110.89 90 top
NOREF#323  -  []  149.14 86.96 90 top
NOREF#324  -  []  149.14 89.5 0 top
NOREF#325  -  []  89.17 121.36 0 top
NOREF#326  -  []  120.46 87.67 90 top
NOREF#327  -  []  10.89 99.12 0 top
NOREF#328  -  []  161.27 70.31 0 top
NOREF#329  -  []  100.93 104.59 0 top
NOREF#330  -  []  90.53 55.07 90 top
NOREF#331  -  []  30.11 82.76 0 top
NOREF#332  -  []  31.51 54.82 0 top
NOREF#333  -  []  42.13 69.55 0 top
NOREF#334  -  []  189.46 77.83 90 top
NOREF#335  -  []  73.13 13.8 90 top
NOREF#336  -  []  112.48 56.43 90 top
NOREF#337  -  []  140.25 117.92 0 top
NOREF#338  -  []  71.86 7.45 0 top
NOREF#339  -  []  84.47 116.28 0 top
NOREF#340  -  []  104.04 68.87 90 top
NOREF#341  -  []  140.95 116.27 90 top
NOREF#342  -  []  42.78 77.62 0 top
NOREF#343  -  []  44.27 116.43 90 top
NOREF#344  -  []  102.41 105.37 90 top
NOREF#345  -  []  97.63 1.09 0 top
NOREF#346  -  []  87.42 122.69 0 top
NOREF#347  -  []  61.4 83.95 90 top
NOREF#348  -  []  145.14 116.27 90 top
NOREF#349  -  []  157.98 31.19 90 top
NOREF#350  -  []  150.59 72.02 90 top
NOREF#351  -  []  86.81 32.82 0 top
NOREF#352  -  []  101.51 136.98 0 top
NOREF#353  -  []  12.03 100.21 90 top
NOREF#354  -  []  157.98 33.73 90 top
NOREF#355  -  []  89.17 123.01 0 top
NOREF#356  -  []  6.47 120.99 0 top
NOREF#357  -  []  147.49 90.85 0 top
NOREF#358  -  []  161.84 89.5 0 top
NOREF#359  -  []  103.9 117.81 0 top
NOREF#360  -  []  129.32 107.07 90 top
NOREF#361  -  []  74.12 136.35 0 top
NOREF#362  -  []  45.61 79.82 90 top
NOREF#363  -  []  155.54 72.02 90 top
NOREF#364  -  []  166.04 24.66 0 top
NOREF#365  -  []  186.96 73.76 0 top
NOREF#366  -  []  58.61 111.16 90 top
NOREF#367  -  []  125.2 110.6 90 top
NOREF#368  -  []  55.76 33.52 0 top
NOREF#369  -  []  24.44 63.52 90 top
NOREF#370  -  []  146.55 133.14 0 top
NOREF#371  -  []  1.51 110.81 0 top
NOREF#372  -  []  188.96 77.08 90 top
NOREF#373  -  []  45.61 68.77 90 top
NOREF#374  -  []  105.16 65.04 90 top
NOREF#375  -  []  49 7.45 0 top
NOREF#376  -  []  26.18 85.42 0 top
NOREF#377  -  []  7.11 115.21 90 top
NOREF#378  -  []  84.49 123.84 0 top
NOREF#379  -  []  133.87 94.19 0 top
NOREF#380  -  []  73.49 3.37 0 top
NOREF#381  -  []  30.9 -25.28 90 top
